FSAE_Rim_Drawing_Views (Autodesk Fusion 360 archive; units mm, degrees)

design "FSAE_Rim_Drawing_Views" references "Hexagon Socket Head Cap Screw DIN 912 - M4 x 0.7 x 16 Steel 4.6 Plain", "Hexagon Nut DIN 934 - M4 x 0.7 Steel 6 Plain"
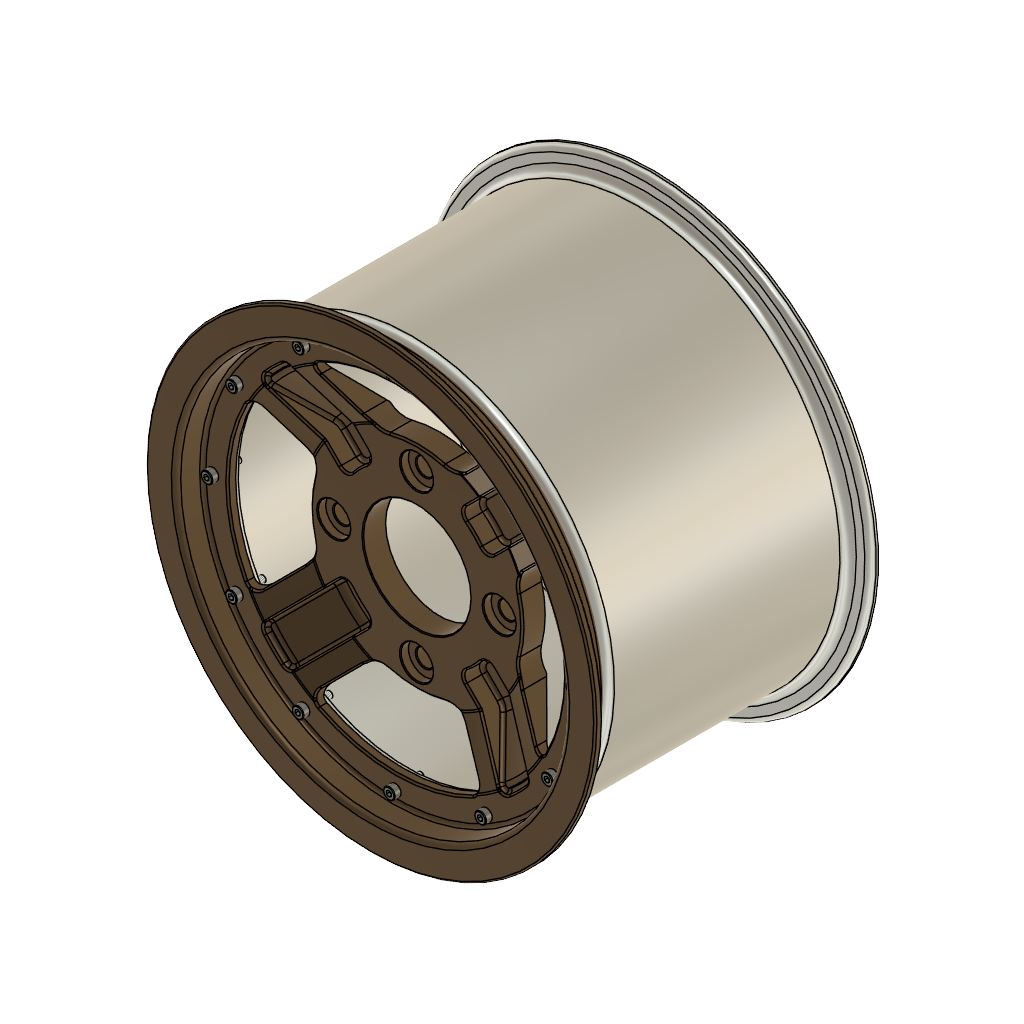
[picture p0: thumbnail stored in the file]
part number: 2026-07-27-09-56-27-671
part number: 2026-08-04-10-59-52-273
part number: 2026-08-04-10-59-52-284
part number: 2026-08-04-10-59-52-289
sketch "Sketch1" plane through (0, 0, 0) normal (1, 0, 0) x axis (0, 1, 0)
  line L1 (153.5, 0) -> (0, 0)
  line L2 (0, 119.5) -> (0, 104)
  line L3 (143.5, 124.5) -> (5, 124.5)
  line L4 (148.5, 134.75) -> (148.5, 129.5)
  line L5 (153.5, 138.25) -> (152, 138.25)
  line L6 (2.5, 119.5) -> (2.5, 104)
  line L7 (143.5, 122) -> (5, 122)
  line L8 (151, 134.75) -> (151, 129.5)
  line L9 (153.5, 135.75) -> (152, 135.75)
  line L10 (2.5, 104) -> (0, 104)
  line L11 (153.5, 135.75) -> (153.5, 138.25)
  arc A1 centre (152, 134.75) radius 3.5 clockwise from (148.5, 134.75) to (152, 138.25)
  arc A2 centre (143.5, 129.5) radius 5 clockwise from (148.5, 129.5) to (143.5, 124.5)
  arc A3 centre (5, 119.5) radius 5 clockwise from (0, 119.5) to (5, 124.5)
  arc A4 centre (5, 119.5) radius 2.5 clockwise from (2.5, 119.5) to (5, 122)
  arc A5 centre (143.5, 129.5) radius 7.5 clockwise from (151, 129.5) to (143.5, 122)
  arc A6 centre (152, 134.75) radius 1 clockwise from (151, 134.75) to (152, 135.75)
  point P1 (0, 0)
  point P2 (0, 0)
  point P4 (0, 104)
  point P3 (153.5, 0)
  point P7 (153.5, 138.25)
  point P6 (148.5, 124.5)
  point P5 (0, 124.5)
  coincident P1 P2
  horizontal L1
  perpendicular L1 L2
  perpendicular L2 L3
  perpendicular L3 L4
  perpendicular L4 L5
  vertical P1 P4
  vertical P3 P7
  tangent L4 A1
  tangent L5 A1
  coincident P6 L3
  coincident P6 L4
  tangent L3 A2
  tangent L4 A2
  coincident P5 L2
  coincident P5 L3
  tangent L2 A3
  tangent L3 A3
  equal A2 A3
  perpendicular L6 L10
  perpendicular L9 L11
  dimension "d1" distance P2 P3 = 153.5
  dimension "d2" = 208
  dimension "d3" = 249
  dimension "d4" = 276.5
  dimension "d5" distance P5 P6 = 148.5
  dimension "d6" radius A1 = 3.5
  dimension "d7" radius A2 = 5
  dimension "d8" = 2.5
revolve "Revolve1" sketch "Sketch1" AlongAngle 360 bodies "FSAE Rim Back"
sketch "Sketch2" plane through (0, 0, 0) normal (0, -1, 0) x axis (1, 0, 0)
  circle C1 centre (0, 0) radius 104
  circle C2 centre (0, 0) radius 119.5
  circle C3 centre (0, 0) radius 112
  circle C4 centre (0, 112) radius 2.15
  point P1 (0, 0)
  point P3 (0, 0)
  point P4 (0, 112)
  coincident P1 P3
  coincident C3 P4
  vertical P3 P4
  dimension "d10" diameter C3 = 224
  dimension "d11" diameter C4 = 4.3
extrude "Extrude1" cut sketch "Sketch2" profile of C4 to an object
circular_pattern "C-Pattern1" TotalAngle 360
canvas "Canvas1"
move "Move1"
sketch "Sketch4" plane through (0, 0, 0) normal (1, 0, 0) x axis (0, 1, 0)
  line L1 (14, 0) -> (0, 0)
  line L2 (14, 72.5) -> (14, 0)
  line L3 (-8, 102.5) -> (14, 72.5)
  line L4 (-8, 124.5) -> (-8, 102.5)
  line L5 (-23.5, 124.5) -> (-8, 124.5)
  line L6 (-23.5, 138) -> (-23.5, 124.5)
  line L7 (-28.25, 138) -> (-23.5, 138)
  line L8 (-28.25, 0) -> (-28.25, 138)
  line L9 (0, 0) -> (-28.25, 0)
  line L10 (-13, 118.1658) -> (-28.25, 119.5)
  line L11 (-13, 102.5) -> (-13, 118.1658)
  line L12 (0, 68.6338) -> (-13, 102.5)
  line L13 (0, 0) -> (0, 68.6338)
  point P1 (0, 0)
  point P2 (0, 0)
  point P11 (0, 0)
  point P12 (-28.25, 119.5)
  point P5 (-8, 102.5)
  point P14 (-13, 102.5)
  point P3 (14, 0)
  point P4 (14, 72.5)
  point P6 (-8, 124.5)
  point P8 (-23.5, 138)
  point P9 (-28.25, 138)
  coincident P1 P2
  horizontal L1
  perpendicular L1 L2
  perpendicular L1 L4
  perpendicular L4 L5
  perpendicular L5 L6
  perpendicular L6 L7
  coincident P1 P11
  collinear L1 L9
  perpendicular L8 L9
  coincident L8 P12
  parallel L8 L11
  vertical L13
  horizontal P5 P14
  dimension "d29" distance P2 P3 = 14
  dimension "d30" = 145
  dimension "d31" = 205
  dimension "d32" = 249
  dimension "d33" = 276
  dimension "d34" distance P4 P6 = 22
  dimension "d35" distance P6 P8 = 15.5
  dimension "d36" distance P8 P9 = 4.75
  dimension "d37" distance L4 L11 = 5
  dimension "d38" angle L12 L13 = 159
  dimension "d39" angle L10 L11 = 95
  dimension "d40" = 239
revolve "Revolve3" sketch "Sketch4" AlongAngle 360 bodies "FSAE Rim Front"
sketch "Sketch5" plane through (0, 0, 0) normal (0, -1, 0) x axis (1, 0, 0)
  circle C1 centre (0, 0) radius 68.6338
  circle C2 centre (0, 0) radius 33
  point P1 (0, 0)
  point P3 (0, 0)
  coincident P1 P3
  dimension "d42" diameter C2 = 66
extrude "Extrude2" cut sketch "Sketch5" profile of C2 to an object
sketch "Sketch6" plane through (0, 0, 0) normal (0, -1, 0) x axis (1, 0, 0)
  circle C1 centre (0, 0) radius 33
  circle C2 centre (0, 0) radius 68.6338
  circle C3 centre (0, 0) radius 50.8
  point P1 (0, 0)
  point P4 (0, 0)
  point P3 (0, 50.8)
  coincident P1 P4
  coincident P3 C3
  vertical P1 P3
  dimension "d45" diameter C3 = 101.6
hole "Hole1" HoleDiameter 10.5 TipAngle 180 CBDepth 5 CBDiameter 20
chamfer "Chamfer2" sketch "Sketch1" distance 0.5
circular_pattern "C-Pattern2" TotalAngle 360
sketch "Sketch7" plane through (0, -13, 0) normal (0, -1, 0) x axis (1, 0, 0)
  circle C1 centre (0, 0) radius 102.5
  circle C2 centre (0, 0) radius 118.1658
  circle C3 centre (0, 0) radius 112
  point P1 (0, 0)
  point P3 (0, 0)
  point P4 (0, 112)
  coincident P1 P3
  coincident C3 P4
  vertical P1 P4
  dimension "d53" diameter C3 = 224
hole "Hole2" HoleDiameter 4.3 TipAngle 180
circular_pattern "C-Pattern3" TotalAngle 360
fillet "Fillet1" radius 1 3 2
chamfer "Chamfer1" distance 0.5
form "Form1" bodies "Tire"
fillet "Fillet2" radius 5
sketch "Sketch8" plane through (0, 0, 0) normal (1, 0, 0) x axis (0, 1, 0)
  line L1 (47.5, 224.911) -> (47.5, 204.911)
  line L2 (57.5, 224.911) -> (47.5, 224.911)
  line L3 (57.5, 204.9943) -> (57.5, 224.911)
  line L4 (87.5, 224.911) -> (87.5, 204.2438)
  line L5 (97.5, 224.911) -> (87.5, 224.911)
  line L6 (97.5, 203.6595) -> (97.5, 224.911)
  line L7 (17.5, 224.911) -> (17.5, 203.6595)
  line L8 (7.5, 224.911) -> (17.5, 224.911)
  line L9 (7.5, 202.9073) -> (7.5, 224.911)
  arc A1 centre (57.5, -395.0057) radius 600 clockwise from (-46, 196) to (161, 196)
  point P2 (-46, 196)
  point P3 (161, 196)
  point P8 (57.5, 204.9943)
  point P9 (87.5, 204.2438)
  point P12 (97.5, 203.6595)
  point P13 (17.5, 203.6595)
  point P16 (7.5, 202.9073)
  point P5 (47.5, 204.911)
  point P1 (0, 0)
  point P6 (47.5, 224.911)
  point P7 (57.5, 224.911)
  horizontal P2 P3
  vertical L1
  perpendicular L1 L2
  midpoint A1 P8
  perpendicular L2 L3
  coincident A1 P9
  parallel L3 L4
  perpendicular L4 L5
  coincident A1 P12
  perpendicular L5 L6
  coincident A1 P13
  perpendicular L5 L7
  perpendicular L7 L8
  coincident A1 P16
  perpendicular L8 L9
  collinear L2 L8
  collinear L2 L5
  equal L2 L8
  equal L2 L5
  coincident A1 P5
  dimension "d68" radius A1 = 600
  dimension "d69" distance P1 P3 = 196
  dimension "d70" distance P1 P2 = 46
  dimension "d71" distance P1 P3 = 161
  dimension "d73" distance P6 P7 = 10
  dimension "d74" distance L1 L7 = 30
  dimension "d75" distance L3 L4 = 30
  dimension "d76" distance P5 P6 = 20
revolve "Revolve4" AlongAngle 360
revolve "Revolve5" sketch "Sketch8" AlongAngle 360
work_plane "WorkPlane1" AlongDistance 275 ExtraOffset 0
sketch "Sketch9" plane through (0, 0, 275) normal (0, 0, 1) x axis (1, 0, 0)
  line L1 (-48.7008, 53.5011) -> (0, -75.7953)
  line L2 (0, 197.5142) -> (-48.7008, 53.5011)
  line L3 (-43.392, 53.5917) -> (4.6791, -74.0329)
  line L4 (4.7365, 195.9124) -> (-43.392, 53.5917)
  line L5 (4.6791, -74.0329) -> (0, -75.7953)
  line L6 (0, 197.5142) -> (4.7365, 195.9124)
  perpendicular L3 L5
  perpendicular L2 L6
  dimension "d80" = 5
step "SurfaceExtend" extendDistance 125
extrude "Extrude3" cut sketch "Sketch9" to an object
circular_pattern "C-Pattern4" countU 30 TotalAngle 360
remove_body "RemoveBody1"
remove_body "RemoveBody2"
work_plane "WorkPlane2" AlongDistance -150 ExtraOffset 0
sketch "Sketch10" plane through (0, -150, 0) normal (0, 1, 0) x axis (1, 0, 0)
  circle C1 centre (0, 0) radius 157.5
  point P1 (0, 0)
  point P2 (0, 0)
  coincident P1 P2
  dimension "d88" diameter C1 = 315
  dimension "d89" Text1-Height = 20
extrude "Extrude4" sketch "Sketch10" blind 2
circular_pattern "C-Pattern5" TotalAngle 360
component_from_bodies "Body->Comp1"
component_from_bodies "Body->Comp2"
component_from_bodies "Body->Comp3"
sketch "Sketch1" plane through (0, -13, 0) normal (0, -1, 0) x axis (1, 0, 0)
  line L1 (0, 103.056) -> (0, 0)
  line L2 (103.056, 0) -> (0, 0)
  line L3 (72.8716, 72.8716) -> (0, 0)
  line L4 (88.3726, 53.0172) -> (60.1041, 24.7487)
  line L5 (53.0172, 88.3726) -> (24.7487, 60.1041)
  circle C1 centre (0, 0) radius 103.056
  circle C2 centre (0, 112) radius 2.15
  circle C3 centre (56, 96.9948) radius 2.15
  circle C4 centre (96.9948, 56) radius 2.15
  circle C5 centre (112, 0) radius 2.15
  circle C6 centre (96.9948, -56) radius 2.15
  circle C7 centre (56, -96.9948) radius 2.15
  circle C8 centre (0, -112) radius 2.15
  circle C9 centre (-56, -96.9948) radius 2.15
  circle C10 centre (-96.9948, -56) radius 2.15
  circle C11 centre (-112, 0) radius 2.15
  circle C12 centre (-96.9948, 56) radius 2.15
  circle C13 centre (-56, 96.9948) radius 2.15
  circle C14 centre (0, 0) radius 116.3331
  arc A1 centre (0, 0) radius 65 clockwise from (0, 65) to (65, 0)
  arc A2 centre (0, 0) radius 65 clockwise from (65, 0) to (0, 65)
  point P2 (0, 0)
  point P16 (0, 0)
  point P17 (0, 103.056)
  point P18 (103.056, 0)
  point P15 (0, 0)
  point P19 (0, 0)
  point P20 (72.8716, 72.8716)
  point P22 (24.7487, 60.1041)
  point P21 (60.1041, 24.7487)
  point P23 (53.0172, 88.3726)
  point P24 (88.3726, 53.0172)
  point P25 (0, 65)
  point P26 (65, 0)
  concentric C1 A1
  coincident P2 P16
  coincident C1 P17
  vertical L1
  coincident C1 P18
  perpendicular L1 L2
  coincident P15 P19
  coincident C1 P20
  coincident P22 A1
  coincident P21 A1
  coincident C1 P23
  coincident C1 P24
  coincident L1 P25
  coincident L2 P26
  concentric A1 A2
  dimension "d95" diameter A1 = 130
  dimension "d96" angle L1 L3 = 45
extrude "Extrude1" cut sketch "Sketch1" profile of C1 L1 L2 L4 L5 A1 to an object
circular_pattern "C-Pattern1" TotalAngle 360
sketch "Sketch2" plane through (0, -13, 0) normal (0, -1, 0) x axis (1, 0, 0)
  line L1 (72.8716, 72.8716) -> (0, 0)
  line L2 (65.9862, 82.9568) -> (25.8367, 42.8073)
  line L3 (82.9568, 65.9862) -> (42.8073, 25.8367)
  arc A1 centre (0, 0) radius 103.056 clockwise from (-53.0172, 88.3726) to (53.0172, 88.3726)
  arc A2 centre (0, 0) radius 103.056 clockwise from (53.0172, 88.3726) to (88.3726, 53.0172)
  arc A3 centre (0, 0) radius 103.056 clockwise from (88.3726, 53.0172) to (88.3726, -53.0172)
  arc A4 centre (0, 0) radius 103.056 clockwise from (88.3726, -53.0172) to (53.0172, -88.3726)
  arc A5 centre (0, 0) radius 103.056 clockwise from (53.0172, -88.3726) to (-53.0172, -88.3726)
  arc A6 centre (0, 0) radius 103.056 clockwise from (-53.0172, -88.3726) to (-88.3726, -53.0172)
  arc A7 centre (0, 0) radius 103.056 clockwise from (-88.3726, -53.0172) to (-88.3726, 53.0172)
  arc A8 centre (0, 0) radius 103.056 clockwise from (-88.3726, 53.0172) to (-53.0172, 88.3726)
  circle C1 centre (0, 112) radius 2.15
  circle C2 centre (56, 96.9948) radius 2.15
  circle C3 centre (96.9948, 56) radius 2.15
  circle C4 centre (112, 0) radius 2.15
  circle C5 centre (96.9948, -56) radius 2.15
  circle C6 centre (56, -96.9948) radius 2.15
  circle C7 centre (0, -112) radius 2.15
  circle C8 centre (-56, -96.9948) radius 2.15
  circle C9 centre (-96.9948, -56) radius 2.15
  circle C10 centre (-112, 0) radius 2.15
  circle C11 centre (-96.9948, 56) radius 2.15
  circle C12 centre (-56, 96.9948) radius 2.15
  circle C13 centre (0, 0) radius 116.3331
  circle C14 centre (0, 0) radius 50
  circle C15 centre (0, 0) radius 106
  point P23 (0, 0)
  point P25 (0, 0)
  point P27 (25.8367, 42.8073)
  point P28 (42.8073, 25.8367)
  point P29 (82.9568, 65.9862)
  point P30 (65.9862, 82.9568)
  parallel L1 L2
  parallel L1 L3
  coincident P23 P25
  concentric C14 C15
  coincident C14 P27
  coincident C14 P28
  coincident C15 P29
  coincident C15 P30
  dimension "d103" distance L1 L2 = 12
  dimension "d104" distance L1 L3 = 12 (= "d103")
  dimension "d105" diameter C14 = 100
  dimension "d106" diameter C15 = 212
extrude "Extrude2" cut sketch "Sketch2" profile of A2 L2 L3 C14 C15 to an object offset 2
fillet "Fillet1" radius 5
fillet "Fillet2" radius 10
fillet "Fillet3" radius 2
circular_pattern "C-Pattern2" TotalAngle 360
fillet "Fillet4" radius 15 5
chamfer "Chamfer1" sketch "Sketch1" distance 1
step "Screw1"
joint "Assemble" alignAngle 0 alignOffsetX 0 alignOffsetY 0 alignOffsetZ 0
step "Screw2"
joint "Assemble" alignAngle 0 alignOffsetX 0 alignOffsetY 0 alignOffsetZ 0
step "Screw3"
joint "Assemble" alignAngle 0 alignOffsetX 0 alignOffsetY 0 alignOffsetZ 0
step "Screw4"
joint "Assemble" alignAngle 0 alignOffsetX 0 alignOffsetY 0 alignOffsetZ 0
step "Screw5"
joint "Assemble" alignAngle 0 alignOffsetX 0 alignOffsetY 0 alignOffsetZ 0
step "Screw6"
joint "Assemble" alignAngle 0 alignOffsetX 0 alignOffsetY 0 alignOffsetZ 0
step "Screw7"
joint "Assemble" alignAngle 0 alignOffsetX 0 alignOffsetY 0 alignOffsetZ 0
step "Screw8"
joint "Assemble" alignAngle 0 alignOffsetX 0 alignOffsetY 0 alignOffsetZ 0
step "Screw9"
joint "Assemble" alignAngle 0 alignOffsetX 0 alignOffsetY 0 alignOffsetZ 0
step "Screw10"
joint "Assemble" alignAngle 0 alignOffsetX 0 alignOffsetY 0 alignOffsetZ 0
step "Screw11"
joint "Assemble" alignAngle 0 alignOffsetX 0 alignOffsetY 0 alignOffsetZ 0
step "Screw12"
joint "Assemble" alignAngle 0 alignOffsetX 0 alignOffsetY 0 alignOffsetZ 0
step "Nut13"
joint "Assemble" alignAngle 0 alignOffsetX 0 alignOffsetY 0 alignOffsetZ 0
step "Nut14"
joint "Assemble" alignAngle 0 alignOffsetX 0 alignOffsetY 0 alignOffsetZ 0
step "Nut15"
joint "Assemble" alignAngle 0 alignOffsetX 0 alignOffsetY 0 alignOffsetZ 0
step "Nut16"
joint "Assemble" alignAngle 0 alignOffsetX 0 alignOffsetY 0 alignOffsetZ 0
step "Nut17"
joint "Assemble" alignAngle 0 alignOffsetX 0 alignOffsetY 0 alignOffsetZ 0
step "Nut18"
joint "Assemble" alignAngle 0 alignOffsetX 0 alignOffsetY 0 alignOffsetZ 0
step "Nut19"
joint "Assemble" alignAngle 0 alignOffsetX 0 alignOffsetY 0 alignOffsetZ 0
step "Nut20"
joint "Assemble" alignAngle 0 alignOffsetX 0 alignOffsetY 0 alignOffsetZ 0
step "Nut21"
joint "Assemble" alignAngle 0 alignOffsetX 0 alignOffsetY 0 alignOffsetZ 0
step "Nut22"
joint "Assemble" alignAngle 0 alignOffsetX 0 alignOffsetY 0 alignOffsetZ 0
step "Nut23"
joint "Assemble" alignAngle 0 alignOffsetX 0 alignOffsetY 0 alignOffsetZ 0
step "Nut24"
joint "Assemble" alignAngle 0 alignOffsetX 0 alignOffsetY 0 alignOffsetZ 0
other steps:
base_feature "Base Feature1" bodies "FSAE Rim Back"
base_feature "Base Feature1" bodies "Tire"
base_feature "Base Feature1" bodies "FSAE Rim Front"
create_component "CreateComponent1"
reparent_decal "ReparentDecal1"
remove_body "RemoveBody3"
create_component "CreateComponent2"
reparent_decal "ReparentDecal2"
remove_body "RemoveBody4"
create_component "CreateComponent3"
reparent_decal "ReparentDecal3"
remove_body "RemoveBody5"
joint_origin "JointOrigin1"
joint_origin "JointOrigin2"
joint_origin "JointOrigin3"
joint_origin "JointOrigin4"
joint_origin "JointOrigin5"
joint_origin "JointOrigin6"
joint_origin "JointOrigin7"
joint_origin "JointOrigin8"
joint_origin "JointOrigin9"
joint_origin "JointOrigin10"
joint_origin "JointOrigin11"
joint_origin "JointOrigin12"
joint_origin "JointOrigin1"
joint_origin "JointOrigin2"
joint_origin "JointOrigin3"
joint_origin "JointOrigin4"
joint_origin "JointOrigin5"
joint_origin "JointOrigin6"
joint_origin "JointOrigin7"
joint_origin "JointOrigin8"
joint_origin "JointOrigin9"
joint_origin "JointOrigin10"
joint_origin "JointOrigin11"
joint_origin "JointOrigin12"
named bodies: "FSAE Rim Back", "FSAE Rim Front", "Tire"

design "Hexagon Nut DIN 934 - M4 x 0.7 Steel 6 Plain"
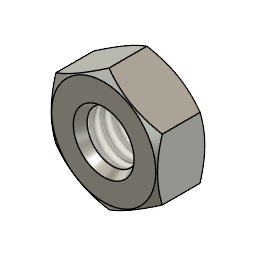
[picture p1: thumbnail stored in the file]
description: Hexagon Nut DIN 934 - M4 x 0.7
part number: DIN 934 - M4 x 0.7 Steel 6 Plain
parameter "adsk_nheig" = 3.2
parameter "adsk_maxdia" = 8.085
parameter "adsk_nomdia" = 4
parameter "adsk_waflat" = 7
parameter "adsk_chamang1" = 30
parameter "adsk_chamang2" = 30
parameter "adsk_beardia" = 6.86 (= "adsk_waflat * 0.98")
sketch "Sketch1" plane through (0, 0, 0) normal (0, 1, 0) x axis (1, 0, 0)
  line L1 (0, -3.2) -> (0, 0)
  line L2 (-3.43, 0) -> (-2, 0)
  line L3 (-4.0425, -0.3536) -> (-3.43, 0)
  line L4 (-4.0425, -2.8464) -> (-4.0425, -0.3536)
  line L5 (-3.43, -3.2) -> (-4.0425, -2.8464)
  line L6 (-2, -3.2) -> (-3.43, -3.2)
  line L7 (-2, 0) -> (-2, -3.2)
  point P3 (0, -3.2)
  point P1 (0, 0)
  point P2 (0, 0)
  point P10 (0, 0)
  point P5 (-3.43, 0)
  point P8 (-3.43, -3.2)
  vertical L1
  coincident L1 P3
  coincident P1 L1
  horizontal L2
  coincident P1 L2
  coincident P2 P10
  coincident P3 L6
  vertical P5 P8
  dimension "d121" = 4 (= "adsk_nomdia")
  dimension "d122" angle L2 L3 = 30 (= "adsk_chamang1")
  dimension "d123" angle L5 L6 = 30 (= "adsk_chamang2")
  dimension "d128" = 8.085 (= "adsk_maxdia")
  dimension "d172" = 6.86 (= "adsk_beardia")
  dimension "d179" distance L2 L6 = 3.2 (= "adsk_nheig")
revolve "Revolve1" sketch "Sketch1" AlongAngle 360
sketch "Sketch8" plane through (0, 0, 3.2) normal (0, 0, 1) x axis (1, 0, 0)
  line L1 (-3.5, 2.0228) -> (-3.5, -2.0228)
  circle C1 centre (0, 0) radius 2
  circle C2 centre (0, 0) radius 4.0425
  point P3 (-3.5, 2.0228)
  point P2 (-3.5, -2.0228)
  point P1 (0, 0)
  coincident P3 C2
  coincident P2 C2
  vertical L1
  dimension "d114" distance P1 L1 = 3.5 (= "adsk_waflat / 2")
extrude "Extrude5" cut sketch "Sketch8" profile of L1 C2 no distance stored
circular_pattern "C-Pattern2" TotalAngle 360
thread "Thread3" ThreadOffset 0 ThreadLength 10
sketch "Sketch12" plane through (0, 0, 0) normal (0, 1, 0) x axis (1, 0, 0)
  line L1 (0, 0) -> (-2, 0)
  line L2 (-2, 0) -> (-1.0762, -1.6)
  line L3 (0, -3.2) -> (-2, -3.2)
  line L4 (-2, -3.2) -> (-1.0762, -1.6)
  line L5 (0, -3.2) -> (0, 0)
  point P4 (-1.0762, -1.6)
  point P7 (-1.0762, -1.6)
  point P2 (-2, 0)
  point P5 (-2, -3.2)
  point P6 (0, -3.2)
  point P9 (0, -3.2)
  point P1 (0, 0)
  point P3 (0, 0)
  horizontal L1
  coincident P4 P7
  vertical P2 P5
  coincident P6 P9
  coincident P1 P3
  perpendicular L3 L5
  dimension "d169" angle L3 L4 = 60
  dimension "d177" distance P2 L5 = 2 (= "adsk_nomdia * 0.5")
  dimension "d178" angle L1 L2 = 60
revolve "Revolve3" sketch "Sketch12" AlongAngle 360
joint_origin "JointOrigin9" OffsetX 0 OffsetY 0 OffsetZ 0 AngleZ 0
joint_origin "JointOrigin10" OffsetX 0 OffsetY 0 OffsetZ 3.2 (= "adsk_nheig") AngleZ 0

design "Hexagon Socket Head Cap Screw DIN 912 - M4 x 0.7 x 16 Steel 4.6 Plain"
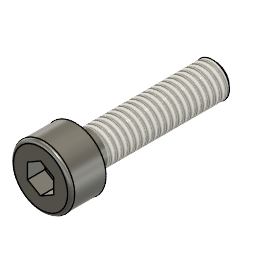
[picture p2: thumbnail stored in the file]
description: Hexagon Socket Head Cap Screw DIN 912 - M4 x 0.7 x 16
part number: DIN 912 - M4 x 0.7 x 16 Steel 4.6 Plain
parameter "adsk_nomlen" = 16
parameter "adsk_headh" = 4
parameter "adsk_headdia" = 7
parameter "adsk_nomdia" = 4
parameter "adsk_philwidth" = 3
parameter "adsk_phildepth" = 2
parameter "adsk_thrlen" = 14.25
parameter "adsk_startlen" = 0.4294
parameter "adsk_endpointdia" = 3.1412
sketch "Sketch1" plane through (0, 0, 0) normal (0, 1, 0) x axis (1, 0, 0)
  line L1 (-2, 16) -> (-2, 0)
  line L2 (0, 16) -> (-2, 16)
  line L3 (0, -4) -> (0, 16)
  line L4 (-3.5, 0) -> (-2, 0)
  line L5 (-3.5, -4) -> (-3.5, 0)
  line L6 (0, -4) -> (-3.5, -4)
  point P1 (0, 0)
  point P4 (0, 16)
  point P7 (0, -4)
  point P5 (-3.5, 0)
  perpendicular L1 L2
  collinear P1 P4 P7
  perpendicular L1 L4
  coincident P1 L4
  vertical L3
  coincident L3 P7
  perpendicular L3 L6
  dimension "d101" distance P1 L2 = 16 (= "adsk_nomlen")
  dimension "d102" distance P5 L6 = 4 (= "adsk_headh")
  dimension "d109" = 7 (= "adsk_headdia")
  dimension "d110" = 4 (= "adsk_nomdia")
revolve "Revolve1" sketch "Sketch1" AlongAngle 360
work_plane "WorkPlane1" AlongDistance 4 (= "adsk_headh")
sketch "Sketch6" plane through (0, 0, 4) normal (0, 0, 1) x axis (1, 0, 0)
  line L1 (1.5, -0.866) -> (0, -1.7321)
  line L2 (1.5, 0.866) -> (1.5, -0.866)
  line L3 (0, 1.7321) -> (1.5, 0.866)
  line L4 (-1.5, 0.866) -> (0, 1.7321)
  line L5 (-1.5, -0.866) -> (-1.5, 0.866)
  line L6 (0, -1.7321) -> (-1.5, -0.866)
  point P1 (0, 0)
  point P8 (0, 0)
  coincident P1 P8
  vertical L2
  dimension "d111" distance L2 L5 = 3 (= "adsk_philwidth")
extrude "Extrude1" cut sketch "Sketch6" no distance stored
extrude "Extrude2" cut of existing geometry no distance stored taper -85
thread "Thread3" ThreadOffset 0 ThreadLength 14.25 (= "min(adsk_thrlen; adsk_nomlen - 0.001 mm)")
fillet "Fillet4" radius 0.4 (= "adsk_nomdia * 0.1")
sketch "Sketch7" plane through (0, 0, 0) normal (0, 1, 0) x axis (1, 0, 0)
  line L1 (-2.04, 15.5706) -> (-2.04, 16)
  line L2 (-1.5706, 16) -> (-2.04, 15.5706)
  line L3 (0, -4) -> (0, 16)
  line L4 (0, 16) -> (-2.04, 16)
  point P5 (0, 16)
  point P7 (0, 16)
  point P4 (-1.5706, 16)
  point P3 (-2.04, 15.5706)
  coincident P5 P7
  perpendicular L3 L4
  coincident P4 L4
  perpendicular L1 L4
  dimension "d104" distance P4 L3 = 1.5706 (= "adsk_endpointdia / 2")
  dimension "d105" distance L1 P7 = 2.04 (= "adsk_nomdia * 0.51")
  dimension "d106" distance P3 L4 = 0.4294 (= "adsk_startlen")
revolve "Revolve3" sketch "Sketch7" AlongAngle 360
joint_origin "JointOrigin2" OffsetX 0 OffsetY 0 OffsetZ 0 AngleZ 0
